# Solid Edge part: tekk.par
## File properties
Username: Kasutaja
Author: Kasutaja
Template: Iso Metric Part.par
Last saved by: Kasutaja
Revision: 4
Application: Solid Edge
Accuracy: 0,990
Face Style: Model Default
Fill Style: Normal
Coef. of Thermal Exp: 0.0
Thermal Conductivity: 0.0
Specific Heat: 0.0
Modulus of Elasticity: 0.0
Poisson's Ratio: 0.0
Yield Stress: 0.0
Ultimate Stress: 0.0
Elongation: 0.0
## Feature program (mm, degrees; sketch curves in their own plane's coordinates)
web network "WebNetwork_3"  Thickness = 1 mm
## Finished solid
Body 1: solid body, 12 faces, 24 edges, 16 vertices, 2 separate solids.
  Faces by surface: plane 12
  Edges by curve: line 24
Bounding box of the edges (mm): 197.453 x 51.320 x 6.000, from (-100.2235, -24.3588, 34) to (97.2293, 26.9608, 40).
Planar faces by outward normal: +x 2, +y 2, +z 2, -x 2, -y 2, -z 2
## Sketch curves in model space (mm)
line (96.7293, -24.3588, 40) -> (96.7293, 26.9608, 40)
line (-99.7235, -24.3588, 40) -> (-99.7235, 26.9608, 40)
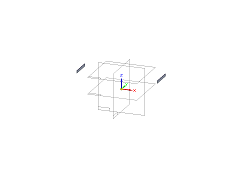
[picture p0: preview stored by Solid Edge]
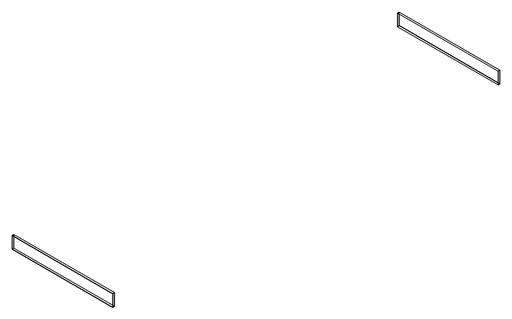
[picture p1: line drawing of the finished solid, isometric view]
